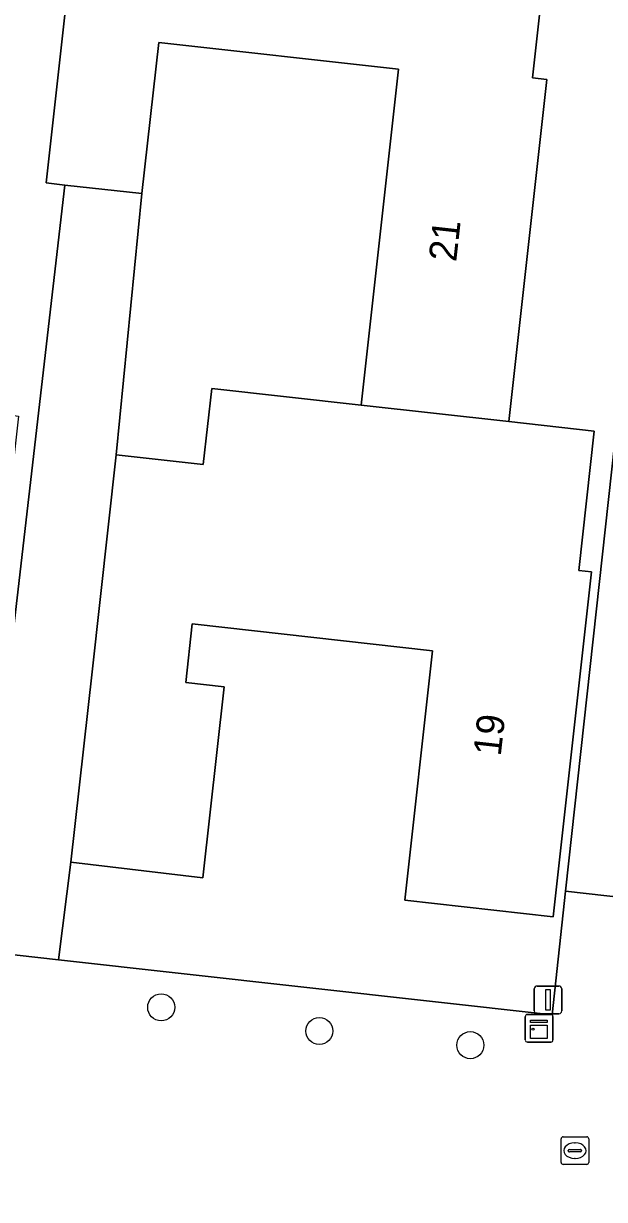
# Model space of a CAD drawing. Extents: x 162396 to 163643, y 386452 to 387406.
# Drawn here: x 162656.78 to 162677.74, y 386667.51 to 386709.97 of the extents above; entities that cross this region are included whole.
import ezdxf

# ---------------------------------------------------------------- set-up
doc = ezdxf.new("R2010")
doc.units = 0
for name, color, linetype in [('IMGEO_Boom', 7, 'Continuous'), ('IMGEO_Erf', 7, 'Continuous'), ('IMGEO_Kast', 7, 'Continuous'), ('IMGEO_Kolk', 7, 'Continuous'), ('IMGEO_Lichtmast', 7, 'Continuous'), ('IMGEO_Pand', 7, 'Continuous'), ('IMGEO_Pand_nummerreeks', 7, 'Continuous'), ('IMGEO_Rijbaan_lokaal_open', 7, 'Continuous'), ('IMGEO_Voetpad_open', 7, 'Continuous')]:
    doc.layers.add(name, color=color, linetype=linetype)

msp = doc.modelspace()

# ---------------------------------------------------------------- linework, layer by layer
at = {"layer": 'IMGEO_Boom'}
for centre in [(162661.745, 386674.448), (162667.45, 386673.592), (162672.901, 386673.081)]:
    msp.add_circle(centre, 0.489, dxfattribs=at)
at = {"layer": 'IMGEO_Erf'}
for points in [[(162658.477, 386679.687), (162658.039, 386676.168), (162675.851, 386674.18), (162676.339, 386678.636), (162678.883, 386701.884), (162678.11, 386701.963), (162679.518, 386715.844), (162676.063, 386716.235), (162675.713, 386713.094), (162675.147, 386708.008), (162675.661, 386707.951), (162674.286, 386695.595), (162677.374, 386695.248), (162676.813, 386690.223), (162677.278, 386690.171), (162675.886, 386677.714), (162670.535, 386678.312), (162671.541, 386687.324), (162662.865, 386688.293), (162662.629, 386686.178), (162664.02, 386686.022), (162663.247, 386679.123)], [(162658.269, 386704.137), (162657.591, 386704.213), (162658.389, 386711.381), (162654.858, 386711.777), (162654.527, 386708.61), (162654.892, 386708.571), (162654.344, 386703.452), (162654.774, 386703.406), (162654.158, 386697.661), (162655.349, 386697.488), (162655.2, 386695.979), (162656.593, 386695.788), (162656.019, 386690.599), (162656.259, 386690.573), (162655.73, 386685.634), (162656.13, 386685.591)], [(162660.124, 386694.395), (162663.263, 386694.045), (162663.57, 386696.79), (162668.958, 386696.188), (162670.307, 386708.321), (162661.655, 386709.283), (162661.048, 386703.828)]]:
    msp.add_lwpolyline(points, close=True, dxfattribs=at)
at = {"layer": 'IMGEO_Kast'}
for p, q in [((162674.883, 386673.268), (162674.883, 386674.109)), ((162674.883, 386674.109), (162674.883, 386673.268)), ((162674.958, 386674.193), (162675.799, 386674.193)), ((162675.799, 386674.193), (162674.958, 386674.193)), ((162675.883, 386674.118), (162675.883, 386673.277)), ((162675.883, 386673.277), (162675.883, 386674.118)), ((162675.808, 386673.193), (162674.967, 386673.193)), ((162674.967, 386673.193), (162675.808, 386673.193))]:
    msp.add_line(p, q, dxfattribs=at)
for points in [[(162675.078, 386673.983), (162675.678, 386673.983), (162675.678, 386673.898), (162675.078, 386673.898), (162675.078, 386673.983)], [(162675.078, 386673.808), (162675.678, 386673.808), (162675.678, 386673.319), (162675.078, 386673.319), (162675.078, 386673.808)]]:
    msp.add_lwpolyline(points, dxfattribs=at)
msp.add_circle((162675.162, 386673.657), 0.0377, dxfattribs=at)
for centre, start, end in [((162674.961, 386674.115), 92.4484, 184.2845), ((162674.961, 386674.115), 92.4484, 184.2845), ((162675.805, 386674.115), 2.4484, 94.2845), ((162675.805, 386674.115), 2.4484, 94.2845), ((162674.961, 386673.271), 182.4484, 274.2845), ((162674.961, 386673.271), 182.4484, 274.2845), ((162675.805, 386673.271), 272.4484, 4.2845), ((162675.805, 386673.271), 272.4484, 4.2845)]:
    msp.add_arc(centre, 0.0779, start, end, dxfattribs=at)
at = {"layer": 'IMGEO_Kolk'}
for p, q in [((162676.175, 386668.847), (162676.175, 386669.699)), ((162676.25, 386669.773), (162677.102, 386669.773)), ((162676.663, 386669.553), (162676.688, 386669.553)), ((162677.176, 386669.699), (162677.176, 386668.847)), ((162676.434, 386669.267), (162676.434, 386669.279)), ((162676.872, 386669.23), (162676.474, 386669.23)), ((162676.477, 386669.316), (162676.875, 386669.316)), ((162676.686, 386668.993), (162676.661, 386668.993)), ((162676.918, 386669.279), (162676.918, 386669.267)), ((162677.102, 386668.773), (162676.25, 386668.773))]:
    msp.add_line(p, q, dxfattribs=at)
for points in [[(162676.175, 386668.847), (162676.175, 386669.699)], [(162676.25, 386669.773), (162677.102, 386669.773)], [(162677.176, 386669.699), (162677.176, 386668.847)], [(162677.102, 386668.773), (162676.25, 386668.773)]]:
    msp.add_lwpolyline(points, dxfattribs=at)
for centre, radius, start, end in [((162676.252, 386669.697), 0.0765, 91.552, 178.448), ((162676.252, 386669.697), 0.0765, 91.552, 178.448), ((162677.1, 386669.697), 0.0765, 1.552, 88.448), ((162677.1, 386669.697), 0.0765, 1.552, 88.448), ((162676.474, 386669.276), 0.0403, 85.8775, 175.7526), ((162676.471, 386669.266), 0.0366, 178.938, 274.7102), ((162676.875, 386669.273), 0.043, 264.8664, 352.4533), ((162676.879, 386669.278), 0.0386, 1.7309, 96.639), ((162676.252, 386668.849), 0.0765, 181.552, 268.448), ((162676.252, 386668.849), 0.0765, 181.552, 268.448), ((162677.1, 386668.849), 0.0765, 271.552, 358.448), ((162677.1, 386668.849), 0.0765, 271.552, 358.448)]:
    msp.add_arc(centre, radius, start, end, dxfattribs=at)
for centre, major_axis, ratio, start_param, end_param in [((162676.662, 386669.273), (-0.387, 0.002), 0.722429, 4.712389, 7.853982), ((162676.687, 386669.273), (-0.39, 0.002), 0.717154, 1.570796, 4.712389)]:
    msp.add_ellipse(centre, major_axis=major_axis, ratio=ratio, start_param=start_param, end_param=end_param, dxfattribs=at)
at = {"layer": 'IMGEO_Lichtmast'}
for p, q in [((162675.21, 386674.316), (162675.21, 386675.116)), ((162675.21, 386675.116), (162675.21, 386674.316)), ((162675.31, 386675.216), (162676.1, 386675.216)), ((162676.1, 386675.216), (162675.31, 386675.216)), ((162676.2, 386675.116), (162676.2, 386674.316)), ((162676.2, 386674.316), (162676.2, 386675.116)), ((162676.1, 386674.216), (162675.31, 386674.216)), ((162675.31, 386674.216), (162676.1, 386674.216))]:
    msp.add_line(p, q, dxfattribs=at)
msp.add_lwpolyline([(162675.63, 386675.091), (162675.78, 386675.091), (162675.78, 386674.341), (162675.63, 386674.341), (162675.63, 386675.091)], dxfattribs=at)
for centre, start, end in [((162675.31, 386675.116), 90, 180), ((162675.31, 386675.116), 90, 180), ((162676.1, 386675.116), 0, 90), ((162676.1, 386675.116), 360, 90), ((162675.31, 386674.316), 180, 270), ((162675.31, 386674.316), 180, 270), ((162676.1, 386674.316), 270, 0), ((162676.1, 386674.316), 270, 0)]:
    msp.add_arc(centre, 0.1, start, end, dxfattribs=at)
at = {"layer": 'IMGEO_Pand'}
for points in [[(162675.656, 386716.282), (162662.298, 386717.793), (162661.929, 386714.628), (162661.529, 386711.031), (162658.389, 386711.381), (162657.591, 386704.213), (162658.269, 386704.137), (162661.048, 386703.828), (162661.655, 386709.283), (162670.307, 386708.321), (162668.958, 386696.188), (162674.286, 386695.595), (162675.661, 386707.951), (162675.147, 386708.008), (162675.713, 386713.094), (162676.063, 386716.235)], [(162658.477, 386679.687), (162663.247, 386679.123), (162664.02, 386686.022), (162662.629, 386686.178), (162662.865, 386688.293), (162671.541, 386687.324), (162670.535, 386678.312), (162675.886, 386677.714), (162677.278, 386690.171), (162676.813, 386690.223), (162677.374, 386695.248), (162674.286, 386695.595), (162668.958, 386696.188), (162663.57, 386696.79), (162663.263, 386694.045), (162660.124, 386694.395), (162659.248, 386686.555)]]:
    msp.add_lwpolyline(points, close=True, dxfattribs=at)
at = {"layer": 'IMGEO_Rijbaan_lokaal_open'}
msp.add_lwpolyline([(162727.566, 386670.164), (162708.666, 386672.324), (162708.493, 386672.348), (162708.151, 386672.418), (162707.816, 386672.519), (162696.344, 386676.37), (162678.572, 386678.387), (162676.339, 386678.636), (162675.851, 386674.18), (162658.039, 386676.168), (162655.154, 386676.489), (162654.796, 386673.146), (162654.582, 386671.122), (162637.224, 386673.17), (162634.219, 386673.532), (162633.669, 386668.517), (162633.436, 386666.294), (162615.958, 386668.261), (162616.786, 386675.351), (162617, 386677.306), (162613.339, 386677.648)], dxfattribs=at)
at = {"layer": 'IMGEO_Voetpad_open'}
for points in [[(162659.248, 386686.555), (162660.124, 386694.395), (162661.048, 386703.828), (162658.269, 386704.137), (162656.13, 386685.591), (162655.154, 386676.489), (162658.039, 386676.168), (162658.477, 386679.687)], [(162678.572, 386678.387), (162681.14, 386701.655), (162678.883, 386701.884), (162676.339, 386678.636)]]:
    msp.add_lwpolyline(points, close=True, dxfattribs=at)

# ---------------------------------------------------------------- texts
at = {"layer": 'IMGEO_Pand_nummerreeks'}
for s, rotation, p in [('21', 83.6512, (162672.389, 386701.342)), ('19', 83.624, (162673.996, 386683.492))]:
    msp.add_text(s, height=1, rotation=rotation, dxfattribs=at).set_placement(p)

doc.saveas('drawing.dxf')
